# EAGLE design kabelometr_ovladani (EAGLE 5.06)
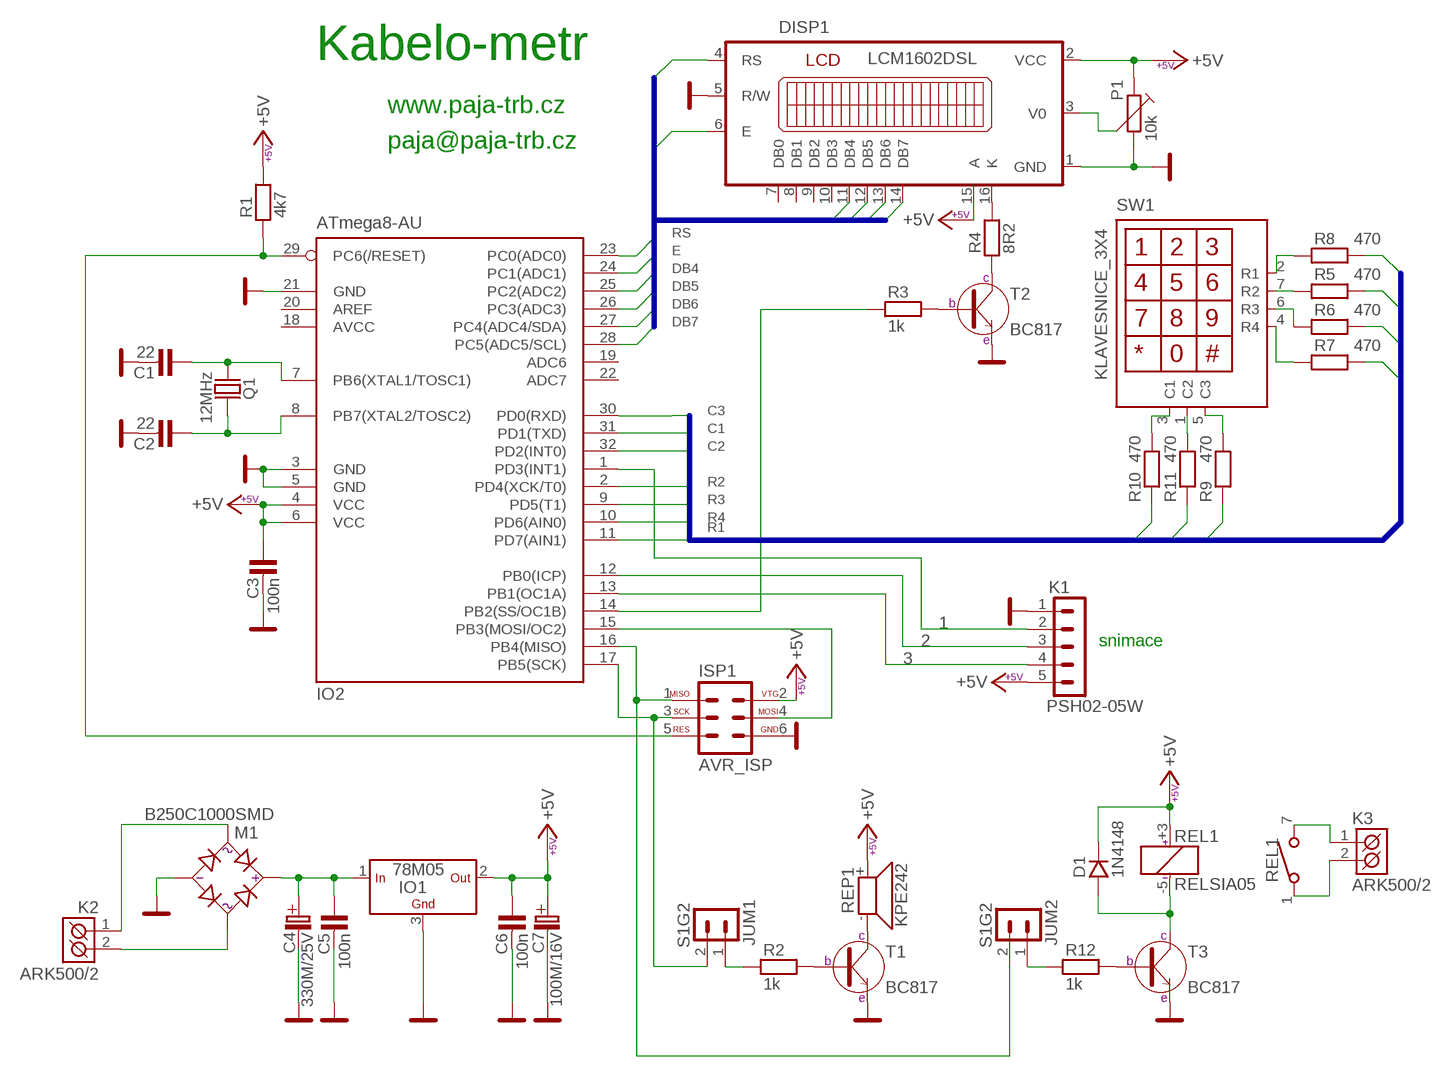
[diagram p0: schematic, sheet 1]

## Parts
C1  22  C-KERAMIK_SMD_1206  [1206]
C2  22  C-KERAMIK_SMD_1206  [1206]
C3  100n  C-KERAMIK_SMD_0805  [0805]
C4  330M/25V  [C_EL_5]
C5  100n  C-KERAMIK_SMD_1206  [1206]
C6  100n  C-KERAMIK_SMD_1206  [1206]
C7  100M/16V  100M/16V_SMD  [C_EL-SMD_D]
D1  1N4148  1N4148_SOD80  [SOD-80]
DISP1  LCM1602DSL  [LCM1602DSL]
IO1  78M05  78_SMD_SMD  [D2PAK]
IO2  ATmega8-AU  MEGA8-AI  [TQFP32-08]
ISP1  AVR_ISP  [MLW06G]
JUM1  S1G2  S1G2_JUMP  [S1G2_JUM]
JUM2  S1G2  S1G2_JUMP  [S1G2_JUM]
K1  PSH02-05W  [PSH02-05W]
K2  ARK500/2  [ARK500/2]
K3  ARK500/2  [ARK500/2]
M1  B250C1000SMD  D-MUSTEK_B250C1000SMD  [DM_DB1S]
P1  10k  TRIMRPT6V  [PT6V]
Q1  12MHz  XTAL_HC-49U_SMD  [HC-49US]
R1  4k7  R_SMD_1206  [1206]
R2  1k  R_SMD_1206  [1206]
R3  1k  R_SMD_1206  [1206]
R4  8R2  R_SMD_1206  [1206]
R5  470  R_SMD_1206  [1206]
R6  470  R_SMD_1206  [1206]
R7  470  R_SMD_1206  [1206]
R8  470  R_SMD_1206  [1206]
R9  470  R_SMD_1206  [1206]
R10  470  R_SMD_1206  [1206]
R11  470  R_SMD_1206  [1206]
R12  1k  R_SMD_1206  [1206]
REL1  RELSIA05  RELSIA  [RELSIA]
REP1  KPE242  [KPE242]
SW1  KLAVESNICE_3X4  [KLAVESNICE_3X4_KB304]
T1  BC817  [SOT-23]
T2  BC817  [SOT-23]
T3  BC817  [SOT-23]

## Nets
1: IO2.1(PD3(INT1)) K1.2
2: IO2.12(PB0(ICP)) K1.3
3: IO2.13(PB1(OC1A)) K1.4
+5V: C3.1 C6.1 C7.+(C_EL+) D1.K DISP1.2(VCC) DISP1.15(A) IO1.2(OUT) IO2.4(VCC) IO2.6(VCC) ISP1.2 K1.5 P1.1 R1.2 REL1.+3(CIVKA:C+) REP1.+
C1: IO2.30(PD0(RXD)) R9.1
C2: IO2.31(PD1(TXD)) R10.1
C3: IO2.32(PD2(INT0)) R11.1
DB4: DISP1.11(DB4) IO2.25(PC2(ADC2))
DB5: DISP1.12(DB5) IO2.26(PC3(ADC3))
DB6: DISP1.13(DB6) IO2.27(PC4(ADC4/SDA))
DB7: DISP1.14(DB7) IO2.28(PC5(ADC5/SCL))
E: DISP1.6(E) IO2.24(PC1(ADC1))
GND: C1.2 C2.2 C3.2 C4.C-(C_EL-) C5.2 C6.2 C7.-(C_EL-) DISP1.1(GND) DISP1.5(R/W) IO1.3(GND) IO2.3(GND) IO2.5(GND) IO2.21(GND) ISP1.6 K1.1 M1.- P1.2 T1.2(E) T2.2(E) T3.2(E)
MISO: IO2.16(PB4(MISO)) ISP1.1 JUM2.2
MOSI: IO2.15(PB3(MOSI/OC2)) ISP1.4
N$1: C2.1 IO2.8(PB7(XTAL2/TOSC2)) Q1.2
N$2: C1.1 IO2.7(PB6(XTAL1/TOSC1)) Q1.1
N$3: R5.1 SW1.7(R2)
N$7: C4.C+(C_EL+) C5.1 IO1.1(IN) M1.+
N$8: K2.2(K2) M1.AC2
N$9: K2.1(K1) M1.AC1
N$10: REP1.- T1.3(C)
N$11: R2.2 T1.1(B)
N$12: R6.1 SW1.6(R3)
N$13: DISP1.3(V0) P1.3
N$14: R3.2 T2.1(B)
N$15: DISP1.16(K) R4.2
N$16: R4.1 T2.3(C)
N$17: R7.1 SW1.4(R4)
N$18: R8.1 SW1.2(R1)
N$19: R9.2 SW1.5(C3)
N$20: R10.2 SW1.3(C1)
N$21: R11.2 SW1.1(C2)
N$22: IO2.14(PB2(SS/OC1B)) R3.1
N$24: JUM1.1 R2.1
N$25: R12.2 T3.1(B)
N$26: JUM2.1 R12.1
N$27: D1.A REL1.-5(CIVKA:C-) T3.3(C)
N$29: K3.2(K2) REL1.1
N$30: K3.1(K1) REL1.7
R1: IO2.2(PD4(XCK/T0)) R5.2
R2: IO2.9(PD5(T1)) R6.2
R3: IO2.10(PD6(AIN0)) R7.2
R4: IO2.11(PD7(AIN1)) R8.2
RESET: IO2.29(PC6(/RESET)) ISP1.5 R1.1
RS: DISP1.4(RS) IO2.23(PC0(ADC0))
SCK: IO2.17(PB5(SCK)) ISP1.3 JUM1.2
Unconnected: DISP1.7(DB0) DISP1.8(DB1) DISP1.9(DB2) DISP1.10(DB3) IO2.19(ADC6) IO2.20(AREF) IO2.22(ADC7)

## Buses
DB[4..7],E,RS
C[1..3],R[1..4]

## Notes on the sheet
- Kabelo-metr
- www.paja-trb.cz
- paja@paja-trb.cz
- snimace

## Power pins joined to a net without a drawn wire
AVCC: IO2.18(AVCC)

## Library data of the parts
C1-C3 C5 C6 = #PaJa_31:C-KERAMIK: Kondenzator - keramicky
C4 = #PaJa_C-el_2:330M/25V
C7 = #PaJa_C-el_2:100M/16V
D1 = #PaJa_31:1N4148: Univerzalni dioda - 0,15A, 75V
DISP1 = #PaJa_displeje:LCM1602DSL: LCD - 2x16 + LED (TME - LCM1602DSL)
IO1 = #PaJa_31:78??: Stabilizátor - 1A a 1,5A ?? - napeti => 05, 06, 08, 09, 12, 15, 18, 20, 24 => 1,5A ?? - napeti => 10, 12, 15, 18 => 1A S ?? - napeti => 05, 09, 10, 12, 15, 18, 24 => 2A T ?? - napeti => 05 => 3A
IO2 = atmel:MEGA8: MICROCONTROLLER 8 Kbytes FLASH, 1 kbytes SRAM, 512 bytes EEPROM, USART, 6-channel 10 bit ADC, 2-channel 8 bit ADC Pin compatible with Atmega48, ATMega88, ATMega168 Source: avr.lbr
ISP1 = #PaJa_31:AVR_ISP: AVR ISP konektor (dle standardu)
JUM1 JUM2 = #PaJa_konektory:S1G2_JUMP: Radove konektory - koliky - 2x
K1 = #PaJa_konektory:PSH02-05: Konektory se zamkem - vidlice - 5pin
K2 K3 = #PaJa_konektory:ARK500/2: Svorkovnice - roztec 5mm - dvojita
M1 = #PaJa_31:D-MUSTEK: Diodovy mustek - Graetz
P1 = #PaJa_31:TRIMR: Trimr
Q1 = #PaJa_31:XTAL_HC-49U: Krystal - 1MHz - 48MHz
R1-R12 = #PaJa_31:R: Rezistor
REL1 = #PaJa_31:RELSIA??: RELE - 1x spinaci, 5V, 12V, 24V max. spinany proud = 0,5A
REP1 = #PaJa_31:KPE242: Piezo-sirenka - 70dB - 3V az 16V
SW1 = #PaJa_prepinace:KLAVESNICE_3X4: Klavesnice - 3x4 KB304 (TME)
T1-T3 = #PaJa_31:BC817: SMD tranzistor - NPN - ekv. BC337

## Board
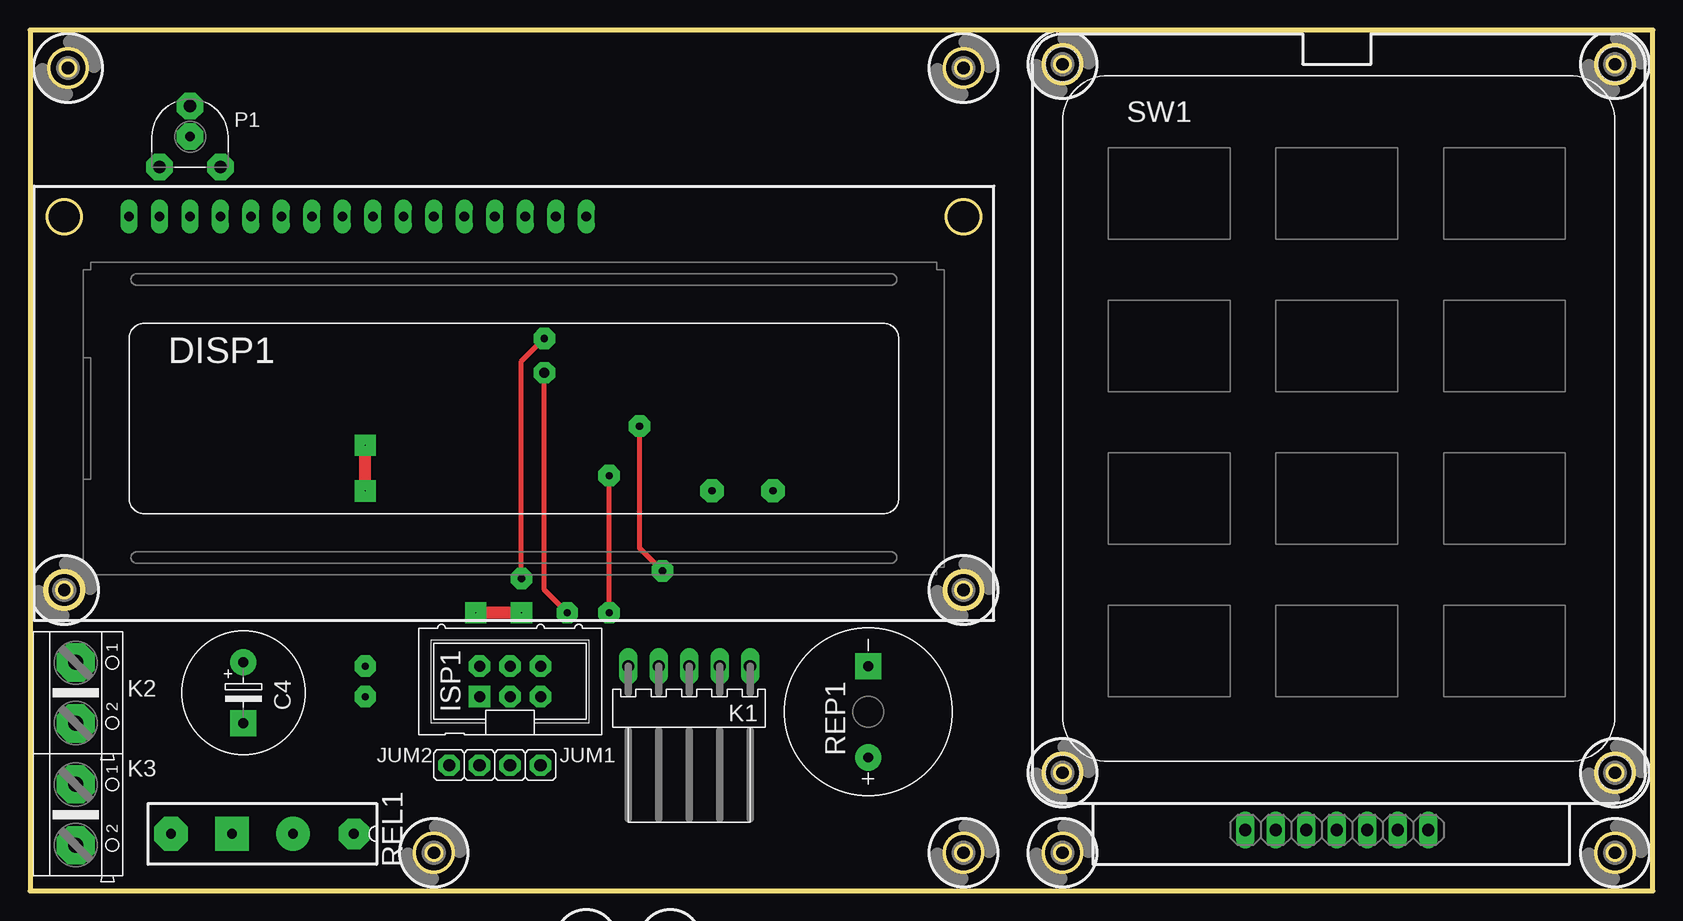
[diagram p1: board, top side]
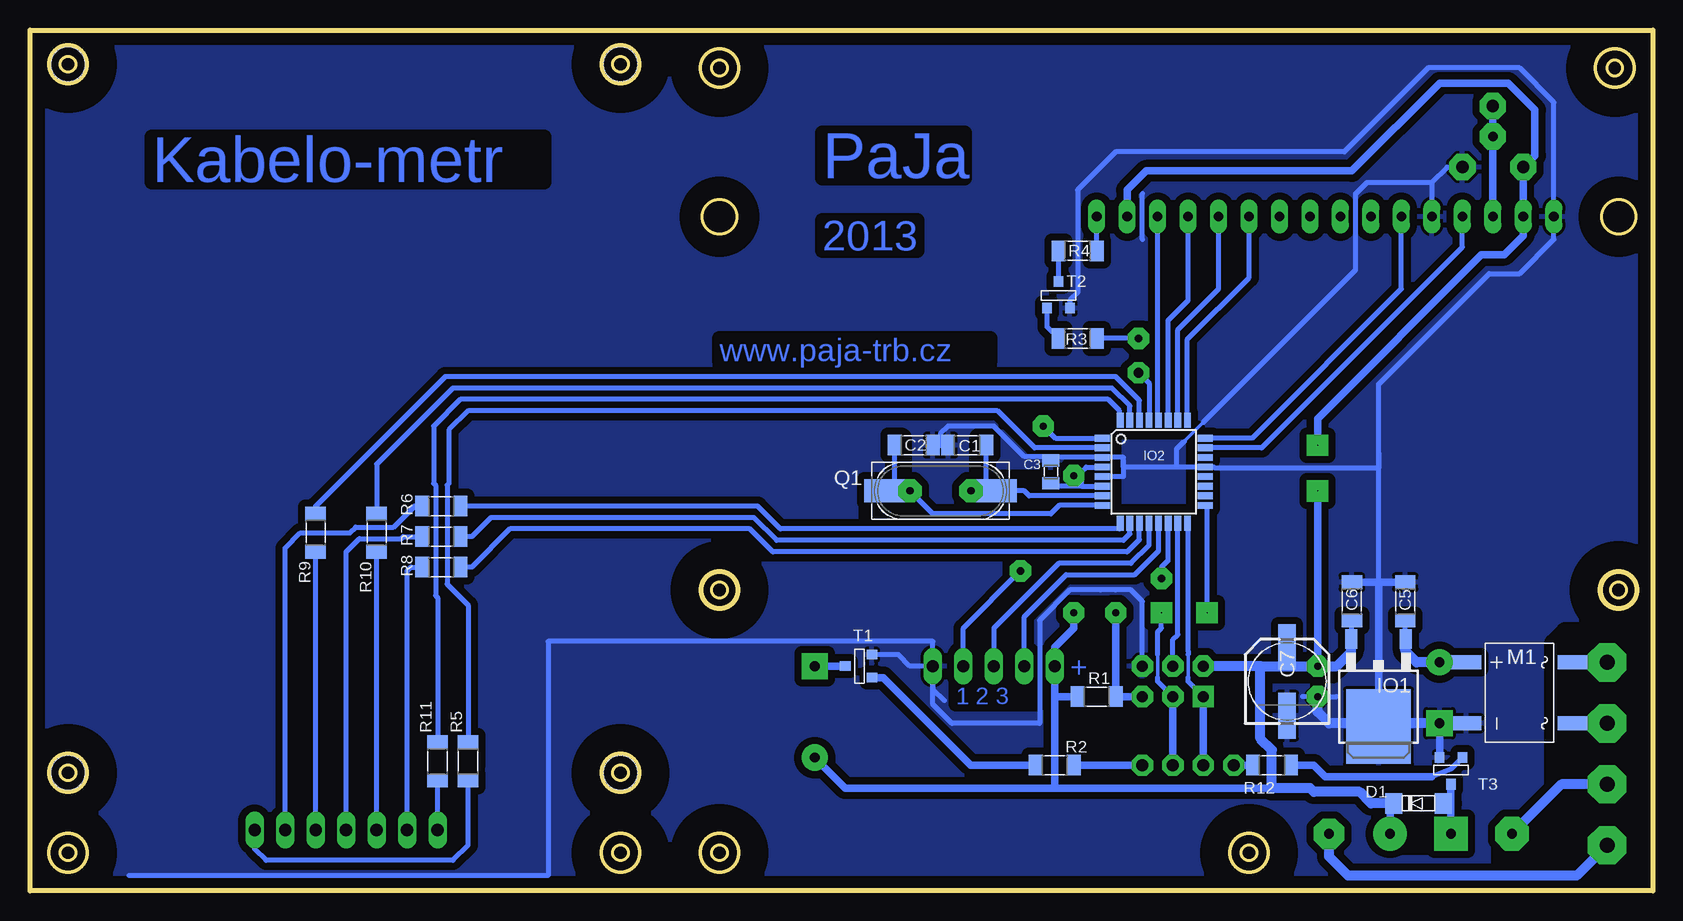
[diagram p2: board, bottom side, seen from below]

Size 135.24 x 71.75 mm. Coordinates in mm from the lower left corner, seen from the top.
Outline: 0,0 135.24,0 135.24,71.75 0,71.75 0,0
Copper layers (1*16): Top 0.035mm / dielectric 1.5mm / Bottom 0.035mm
Design rules "default": minimum track width 10mil, minimum drill 24mil, track to track 8mil, track to pad 8mil, pad to pad 8mil, via to via 8mil, smd to smd 8mil, copper to edge 40mil, drill to drill 8mil, minimum pad ring 10mil, minimum via ring 8mil, stop-mask expansion 4mil, vias tented up to drill 0mil, thermal gap 10mil
bRestrict: 22 lines

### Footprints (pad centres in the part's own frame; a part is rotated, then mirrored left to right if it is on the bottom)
1206 = smd 1.143 x 1.702: 1 -1.587,0; 2 1.587,0
0805 = smd 1.016 x 1.422: 1 -0.953,0; 2 0.953,0
C_EL_5 = drill 0.813 pad 2.184 round: C+ -2.54,0 | drill 0.813 pad 2.184 square: C- 2.54,0
C_EL-SMD_D = smd 3.81 x 1.473: + 2.857,0; - -2.857,0
SOD-80 = smd 1.397 x 1.702: A 1.905,0; K -2.223,0
LCM1602DSL = drill 0.813 pad 1.422 long: 1 -32.068,16.828; 2 -29.527,16.828; 3 -26.988,16.828; 4 -24.448,16.828; 5 -21.907,16.828; 6 -19.367,16.828; 7 -16.828,16.828; 8 -14.287,16.828; 9 -11.748,16.828; 10 -9.207,16.828; 11 -6.668,16.828; 12 -4.128,16.828; 13 -1.587,16.828; 14 0.953,16.828; 15 3.493,16.828; 16 6.032,16.828 | hole 2.8: -37.465,-14.287; 37.465,-14.287; 37.465,16.828; -37.465,16.828
D2PAK = smd 1 x 1.6: 1 -2.28,-4.8; 2 2.28,-4.8 | smd 5.4 x 6.2: 3 0,2.5
TQFP32-08 = smd 1.27 x 0.559: 1 -4.293,2.8; 2 -4.293,2; 3 -4.293,1.2; 4 -4.293,0.4; 5 -4.293,-0.4; 6 -4.293,-1.2; 7 -4.293,-2; 8 -4.293,-2.8; 17 4.293,-2.8; 18 4.293,-2; 19 4.293,-1.2; 20 4.293,-0.4; 21 4.293,0.4; 22 4.293,1.2; 23 4.293,2; 24 4.293,2.8 | smd 0.559 x 1.27: 9 -2.8,-4.293; 10 -2,-4.293; 11 -1.2,-4.293; 12 -0.4,-4.293; 13 0.4,-4.293; 14 1.2,-4.293; 15 2,-4.293; 16 2.8,-4.293; 25 2.8,4.293; 26 2,4.293; 27 1.2,4.293; 28 0.4,4.293; 29 -0.4,4.293; 30 -1.2,4.293; 31 -2,4.293; 32 -2.8,4.293
MLW06G = drill 0.914 pad 1.778 square: 1 -2.54,-1.27 | drill 0.914 pad 1.778 octagon: 2 -2.54,1.27; 3 0,-1.27; 4 0,1.27; 5 2.54,-1.27; 6 2.54,1.27
S1G2_JUM = drill 1.016 pad 1.778 octagon: 1 -1.27,0; 2 1.27,0
PSH02-05W = drill 1.016 pad 1.422 long: 1 -5.08,0; 2 -2.54,0; 3 0,0; 4 2.54,0; 5 5.08,0
ARK500/2 = drill 1.27 pad 3.2 octagon: 1 -2.54,0; 2 2.54,0
DM_DB1S = smd 1.146 x 2.54: + -2.54,-4.445; - 2.54,-4.445; AC1 -2.54,4.445; AC2 2.54,4.445
PT6V = drill 1.016 pad 2.184 octagon: 1 -2.54,-2.54; 2 2.54,-2.54; 3 0,2.54
HC-49US = smd 3.81 x 1.93: 1 -4.445,0; 2 4.445,0
RELSIA = drill 0.813 pad 2.54 octagon: 1 -7.62,0 | drill 0.813 pad 2.8 octagon: 7 7.62,0 | drill 0.813 pad 2.8 round: +3 -2.54,0 | drill 0.813 pad 2.8 square: -5 2.54,0
KPE242 = drill 0.813 pad 2.184 round: + -3.81,0 | drill 0.813 pad 2.184 square: - 3.81,0
KLAVESNICE_3X4_KB304 = drill 1.016 long: 1 -7.62,-34.29; 2 -5.08,-34.29; 3 -2.54,-34.29; 4 0,-34.29; 5 2.54,-34.29; 6 5.08,-34.29; 7 7.62,-34.29 | hole 2.8: -22.86,-29.527; 23.177,-29.527; 23.177,29.527; -22.86,29.527
SOT-23 = smd 0.787 x 0.889: 1 -0.953,-0.953; 2 0.953,-0.953; 3 0,1.27
HOLE_3,0 = hole 3.2: 0,0

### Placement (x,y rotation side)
C1  57.15,37.15 180 bottom
C2  61.59,37.15 0 bottom
C3  50.16,34.92 90 bottom
C4  17.78,16.51 270 top
C5  20.64,24.13 90 bottom
C6  25.08,24.13 90 bottom
C7  30.48,17.46 90 bottom
D1  19.37,7.3 0 bottom
DISP1  40.32,39.37 0 top
IO1  22.86,16.19 180 bottom
IO2  41.59,34.92 0 bottom
ISP1  40.01,17.46 0 top
JUM1  41.27,10.48 180 top
JUM2  36.2,10.48 0 top
K1  54.93,18.73 180 top
K2  3.81,16.51 270 top
K3  3.81,6.35 270 top
M1  11.11,16.51 270 bottom
P1  13.34,62.87 0 top
Q1  59.37,33.34 180 bottom
R1  46.35,16.19 180 bottom
R2  49.85,10.48 180 bottom
R3  47.94,46.04 180 bottom
R4  47.94,53.34 0 bottom
R5  98.74,10.79 90 bottom
R6  100.97,32.07 0 bottom
R7  100.97,29.53 0 bottom
R8  100.97,26.99 0 bottom
R9  111.44,29.84 270 bottom
R10  106.36,29.84 270 bottom
R11  101.28,10.79 270 bottom
R12  31.75,10.48 0 bottom
REL1  19.37,4.76 180 top
REP1  69.85,14.92 90 top
SW1  108.9,39.37 0 top
T1  66.04,18.73 90 bottom
T2  49.53,49.53 0 bottom
T3  16.83,10.16 180 bottom
U$1  [HOLE_3,0]  2.86,25.08 0 top
U$2  [HOLE_3,0]  77.79,25.08 0 top
U$3  [HOLE_3,0]  77.79,68.58 0 top
U$4  [HOLE_3,0]  3.17,68.58 0 top
U$5  [HOLE_3,0]  33.66,3.17 0 top
U$6  [HOLE_3,0]  86.04,68.9 0 top
U$7  [HOLE_3,0]  132.08,68.9 0 top
U$8  [HOLE_3,0]  132.08,9.84 0 top
U$9  [HOLE_3,0]  132.08,3.17 0 top
U$10  [HOLE_3,0]  86.04,9.84 0 top
U$11  [HOLE_3,0]  86.04,3.17 0 top
U$12  [HOLE_3,0]  77.79,3.17 0 top
U$13  [KP23_Z33]  69.85,40.64 0 top

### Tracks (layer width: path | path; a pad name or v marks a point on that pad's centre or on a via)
1  (via drill 0.6 pad 1.78)
  Top 0.406: v52.7,26.67 50.8,28.57 v50.8,38.73
  Bottom 0.406: K1.2 57.47,21.91 v52.7,26.67 | IO2.1 49.79,37.73 v50.8,38.73
2
  Bottom 0.406: K1.3 54.93,21.91 49.53,27.3 43.5,27.3 41.99,28.81 IO2.12
3
  Bottom 0.406: K1.4 52.39,22.86 48.9,26.35 43.18,26.35 41.19,28.34 IO2.13
+5V  (via drill 0.1 pad 1.78, 0.6 pad 1.78)
  Top 0.406: v48.26,23.18 v48.26,34.61
  Top 1.016: v27.94,33.34 v27.94,37.15
  Bottom 0.406: C6.1 25.08,20.99 IO1.2 | 47.62,33.73 IO2.6 | 47.62,34.61 47.62,33.73 | 47.62,34.61 47.62,34.92 47.23,35.33 IO2.4 | 47.62,33.73 49.92,33.73 C3.1 | v48.26,34.61 47.62,34.61
  Bottom 0.61: REL1.+3 21.91,7.3 D1.K | DISP1.15 43.81,58.42 42.23,60.01 25.08,60.01 17.78,67.31 12.06,67.31 9.84,65.09 9.84,61.28 P1.1 DISP1.2 10.79,54.61 12.38,53.02 14.29,53.02 27.94,39.37 v27.94,37.15 | 31.75,8.57 49.85,8.57 | 49.85,8.57 67.31,8.57 REP1.+ | 49.85,8.57 49.85,16.19 | 49.85,16.19 K1.5 49.85,20.32 48.26,21.91 v48.26,23.18 | v27.94,18.73 v27.94,33.34 | 49.85,16.19 R1.2
  Bottom 0.813: 21.91,7.3 23.5,7.3 24.45,8.26 28.26,8.26 28.57,8.57 31.75,8.57 31.75,11.75 32.7,12.7 32.7,18.73 | IO1.2 25.14,19.95 26.35,18.73 v27.94,18.73 30.48,18.73 | 32.7,18.73 ISP1.2 | 32.7,18.73 30.48,18.73 | 30.48,18.73 C7.+
C1
  Bottom 0.406: IO2.30 42.79,40.89 44.77,42.86 100.65,42.86 111.44,32.07 R9.1
C2
  Bottom 0.406: R10.1 106.36,35.56 100.01,41.91 45.09,41.91 43.59,40.42 IO2.31
C3
  Bottom 0.406: IO2.32 44.45,39.27 44.45,40.01 45.4,40.96 99.38,40.96 101.6,38.73 101.6,33.97 101.44,33.81 101.44,24.61 101.28,24.45 R11.1
DB4
  Bottom 0.406: DISP1.11 33.66,51.12 38.79,45.98 IO2.25
DB5
  Bottom 0.406: DISP1.12 36.2,50.16 39.59,46.77 IO2.26
DB6
  Bottom 0.406: DISP1.13 38.73,49.21 40.39,47.55 IO2.27
DB7
  Bottom 0.406: DISP1.14 41.27,39.22 IO2.28
E
  Bottom 0.406: DISP1.6 20.95,50.16 33.4,37.73 IO2.24
GND  (via drill 0.6 pad 1.78)
  Bottom 0.305: 39.05,37.47 37.47,39.05
  Bottom 0.406: P1.2 17.14,60.33 18.41,59.05 | 18.41,59.05 DISP1.5 | IO1.3 22.58,13.97 20.32,13.97 22.86,13.97 | ISP1.6 42.55,24.13 43.5,25.08 44.77,25.08 | 44.77,25.08 46.04,25.08 | IO2.5 44.13,34.52 44.13,35.88 | 44.13,35.88 44.13,36.12 IO2.3 49.92,36.12 C3.2 50.16,36.2 52.39,36.2 54.93,38.73 58.74,38.73 59.37,38.1 59.37,37.15 | 39.69,35.33 IO2.21 36.59,35.33 36.51,35.24 22.86,35.24 22.86,36.51 | 39.69,35.33 44.13,35.33 44.13,35.88 | 59.37,37.15 C1.2 | 59.37,37.15 C2.2 | 22.86,25.72 22.86,34.92 | 22.86,34.92 22.86,35.33 | 22.86,34.92 22.86,36.51 | 22.86,36.51 22.86,42.23 13.65,51.44 11.11,51.44 8.26,54.29 DISP1.1 8.26,65.72 11.11,68.58 18.73,68.58 25.72,61.59 44.77,61.59 47.94,58.42 47.94,49.85 48.58,49.21 T2.2 | K1.1 61.91,18.73 62.87,19.68 T1.2 | K1.1 60.01,16.83 59.05,15.88 | 44.77,25.08 48.58,25.08 51.12,22.54 51.12,13.97 58.42,13.97 60.01,15.56 K1.1 | 39.05,37.47 39.69,36.83 39.69,35.33 | 37.47,39.05 24.77,51.75 24.77,58.1 23.81,59.05 18.41,59.05 | 127,1.27 92.08,1.27 92.08,20.8 60.01,20.8 K1.1 | 42.55,54.29 42.55,58.1 | 26.35,16.19 v27.94,16.19 29.21,16.19
  Bottom 0.61: 22.86,25.72 C5.2 | 22.86,25.72 C6.2 | 22.86,13.97 22.86,25.72 | T3.2 C4.C-
  Bottom 0.813: M1.- C4.C- 20.32,13.97 | v27.94,16.19 27.94,14.92 26.99,13.97 22.86,13.97
  pour Bottom (isolate 0.61): 0,0 0,71.75 135.25,71.75 135.25,0
MISO
  Bottom 0.305: 38.73,17.78 38.73,20
  Bottom 0.406: ISP1.1 38.73,17.46 38.73,17.78 | IO2.16 38.73,30.63 38.73,20 38.73,19.68
  Bottom 0.61: JUM2.2 ISP1.1
MOSI
  Bottom 0.406: ISP1.4 40.01,20.95 39.59,21.37 IO2.15
N$1  (via drill 0.6 pad 1.93)
  Bottom 0.406: IO2.8 49.47,32.12 50.16,31.43 60.01,31.43 v61.91,33.34 63.18,33.34 | 63.18,33.34 Q1.2 | 63.18,33.34 C2.1
N$2  (via drill 0.6 pad 1.93)
  Bottom 0.406: IO2.7 51.98,32.92 52.39,33.34 55.56,33.34 | 55.56,33.34 Q1.1 | 55.56,33.34 C1.1 | 55.56,33.34 v56.83,33.34
N$3
  Bottom 0.406: R5.1 98.74,3.81 100.01,2.54 115.57,2.54 116.52,3.49 SW1.7
N$4  (via drill 0.6 pad 2.54)
  other vias: 77.79,56.2
N$5  (via drill 0.6 pad 2.54)
  other vias: 2.86,56.2
N$6  (via drill 0.6 pad 2.54)
  other vias: 2.86,25.08
N$7
  Bottom 0.406: 20.64,20.93 IO1.1 20.64,20.99 C5.1
  Bottom 0.813: M1.+ C4.C+ 19.68,19.05 20.64,20 20.64,20.93
N$8
  Bottom 0.813: K2.2 M1.AC2
N$9
  Bottom 0.813: K2.1 M1.AC1
N$10
  Bottom 0.61: T1.3 REP1.-
N$11
  Bottom 0.61: T1.1 64.14,17.78 56.83,10.48 R2.2
N$12
  Bottom 0.406: SW1.6 113.98,28.57 112.71,29.84 108.58,29.84 108.11,30.32 104.93,30.32 103.19,32.07 R6.1
N$13  (via drill 0.81 pad 2.18)
  Bottom 0.61: DISP1.3 v13.34,62.87 P1.3
N$14
  Bottom 0.406: T2.1 50.48,46.99 R3.2
N$15
  Bottom 0.406: R4.2 DISP1.16
N$16
  Bottom 0.406: T2.3 R4.1
N$17
  Bottom 0.406: R7.1 104.14,29.53 104.3,29.37 107.79,29.37 108.9,28.26 SW1.4
N$18
  Bottom 0.406: SW1.2 103.82,26.67 103.5,26.99 R8.1
N$19
  Bottom 0.406: SW1.5 R9.2
N$20
  Bottom 0.406: SW1.3 R10.2
N$21
  Bottom 0.406: SW1.1 R11.2
N$22  (via drill 0.6 pad 1.78)
  Top 0.406: v40.96,26.04 40.96,44.13 v42.86,46.04
  Bottom 0.406: IO2.14 40.39,27.55 40.96,26.99 v40.96,26.04 | v42.86,46.04 R3.1
N$23  (via drill 0.6 pad 2.54)
  other vias: 77.79,25.08
N$24
  Bottom 0.61: JUM1.1 R2.1
N$25
  Bottom 0.406: T3.1 16.83,10.16 18.41,9.53
  Bottom 0.61: 18.41,9.53 27.3,9.53 28.26,10.48 R12.2
N$26
  Bottom 0.61: JUM2.1 R12.1
N$27
  Bottom 0.406: 16.83,7.3 D1.A
  Bottom 0.61: REL1.-5 16.83,7.3 T3.3
N$29
  Bottom 0.813: K3.2 6.35,1.27 25.4,1.27 26.99,2.86 REL1.1
N$30
  Bottom 0.813: K3.1 7.62,8.89 REL1.7
R1
  Bottom 0.406: IO2.2 51.53,36.92 54.61,40.01 98.74,40.01 100.33,38.42 100.33,33.97 100.49,33.81 100.49,25.56 98.74,23.81 R5.2
R2
  Bottom 0.406: IO2.9 44.39,30.22 44.45,30.16 72.71,30.16 74.61,32.07 R6.2
R3
  Bottom 0.406: IO2.10 43.59,29.75 44.13,29.21 73.03,29.21 74.93,31.11 96.84,31.11 98.42,29.53 R7.2
R4
  Bottom 0.406: IO2.11 42.79,29.28 43.81,28.26 73.34,28.26 75.25,30.16 95.25,30.16 98.42,26.99 R8.2
RESET  (via drill 0.6 pad 1.78, 0.81 pad 1.78)
  Top 0.406: v44.77,23.18 42.86,25.08 v42.86,43.18
  Bottom 0.406: IO2.29 41.99,42.31 v42.86,43.18
  Bottom 0.61: ISP1.5 R1.1 v44.77,23.18
RS
  Bottom 0.406: DISP1.4 15.88,53.66 32.61,36.92 IO2.23
SCK  (via drill 0.1 pad 1.78)
  Top 1.016: v40.96,23.18 v37.15,23.18
  Bottom 0.305: 41.27,17.78 41.27,19.68
  Bottom 0.406: ISP1.3 41.27,17.46 41.27,17.78 | v40.96,23.18 40.96,21.91 41.27,21.59 41.27,19.68 | v37.15,23.18 37.15,31.97 arc-90 IO2.17
  Bottom 0.61: JUM1.2 ISP1.3

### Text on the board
Bottom: PaJa | Kabelo-metr | 2013 | www.paja-trb.cz | + | 1 2 3
PaJa: www.paja-trb.cz
montazniotvory: 7mm | piezo
stitek: Out rele | AC/DC | max. 0,5A | 7-12V | Kabelo-metr | # | Zpet | Enter | www.paja-trb.cz | (C) PaJa-trb 2013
